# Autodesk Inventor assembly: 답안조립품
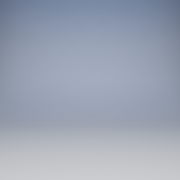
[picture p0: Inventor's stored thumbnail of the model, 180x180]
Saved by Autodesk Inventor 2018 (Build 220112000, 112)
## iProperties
Created: 2020-07
Part Number: 답안조립품
Material: 일반
Document SubType Name: Assembly
Designer: Admin
Author: Admin
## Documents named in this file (1)
- C:\Users\Admin\Desktop\700707V1010\답안조립품.iam
